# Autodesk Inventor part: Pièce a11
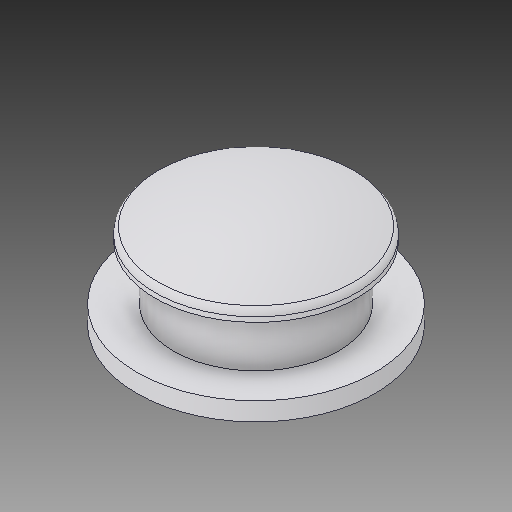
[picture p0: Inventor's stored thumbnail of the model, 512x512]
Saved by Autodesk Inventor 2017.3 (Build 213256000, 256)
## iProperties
Created: 2007-12
Part Number: Pièce a11
Material: solidworks materials|Alliage 7079|22
Document SubType Name: Modeling
Designer: ficho
Appearance: 227,227,233
Author: ficho
Sending System: SolidWorks 2009
Last Author: christophe
Last Saved: 2011-02-10
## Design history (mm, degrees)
feature "Congé2"
node "Solide1"
